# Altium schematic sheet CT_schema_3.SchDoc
size 360 x 214 mm
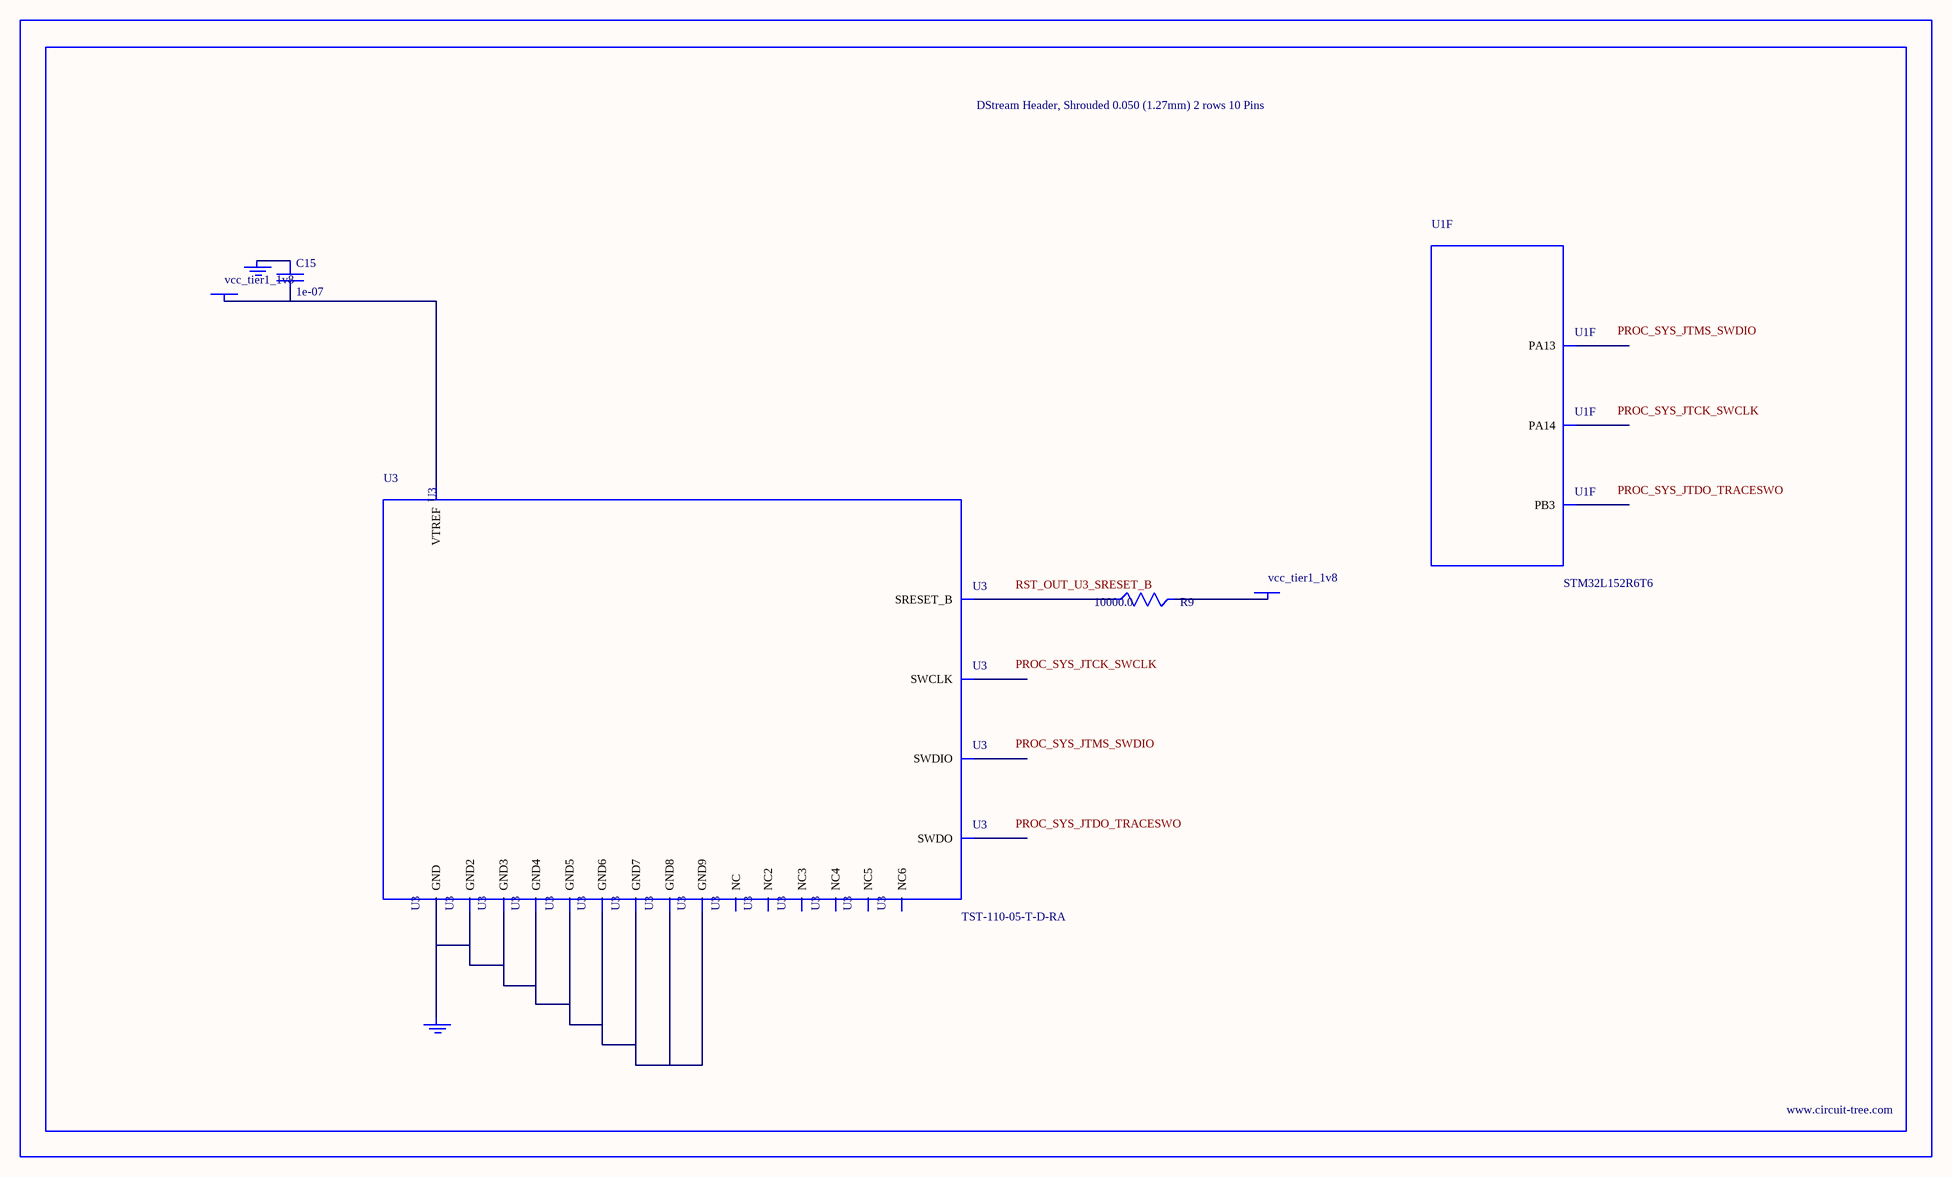
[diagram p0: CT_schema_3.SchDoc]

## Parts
BORDER2  (no value)
C15  1e-07  [C0402]
GND_INSTANCE_2_0  (no value)
GND_INSTANCE_2_1  (no value)
POWER_INSTANCE_2_0  vcc_tier1_1v8
POWER_INSTANCE_2_1  vcc_tier1_1v8
R9  10000.0  [R0603]
U1  STM32L152R6T6  [LQFP64]  (part F of 7)
U3  TST-110-05-T-D-RA  [TST-110-05-T-D-RA]

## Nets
NetC15_1: C15.1 GND_INSTANCE_2_0.0(GND)
NetC15_2: C15.2 POWER_INSTANCE_2_0.0(PWR) U3.1(VTREF)
NetGND_INSTANCE_2_1_0: GND_INSTANCE_2_1.0(GND) U3.4(GND) U3.6(GND2) U3.8(GND3) U3.10(GND4) U3.12(GND5) U3.14(GND6) U3.16(GND7) U3.18(GND8) U3.20(GND9)
NetPOWER_INSTANCE_2_1_0: POWER_INSTANCE_2_1.0(PWR) R9.2
NetR9_1: R9.1 U3.15(SRESET_B)

Not connected (* = marked no-connect by the designer): U1 46(PA13) 49(PA14) 55(PB3); U3 2(NC) 3(NC2) 5(NC3) 7(SWDIO) 9(SWCLK) 11(NC4) 13(SWDO) 17(NC5) 19(NC6)

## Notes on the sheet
- Labels drawn without touching a wire or pin: PROC_SYS_JTCK_SWCLK, PROC_SYS_JTDO_TRACESWO, PROC_SYS_JTMS_SWDIO, RST_OUT_U3_SRESET_B

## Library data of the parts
BORDER2 = BORDER_PAGE2
C15 = C0402C104K3RACTU
GND_INSTANCE_2_0 GND_INSTANCE_2_1 = GND
POWER_INSTANCE_2_0 POWER_INSTANCE_2_1 = PWR
R9 = RC0603JR-0710KL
